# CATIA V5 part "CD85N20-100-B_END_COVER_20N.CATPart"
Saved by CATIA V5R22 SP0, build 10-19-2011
Part number: CD85N20-100-B_END_COVER_20N
Revision: ANY
Definition: UNKNOWN
Nomenclature: CD85N20-100-B_END_COVER_20N
Source: Unknown
Bounding box of the stored display mesh (mm): x -12 to 12, y -12 to 12, z 0 to 35
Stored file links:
  D:\PER\CAO_PER_MODIF_2025\CAO_PER_pick&place_2024P\Sous_Ensemble_Flacon\CD85N20-100-B_END_COVER_20N.CATPart
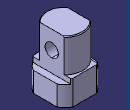
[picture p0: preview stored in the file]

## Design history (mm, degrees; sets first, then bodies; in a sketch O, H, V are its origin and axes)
Body1 "E-EXTEND" (main body)
  Solid1: solid without history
